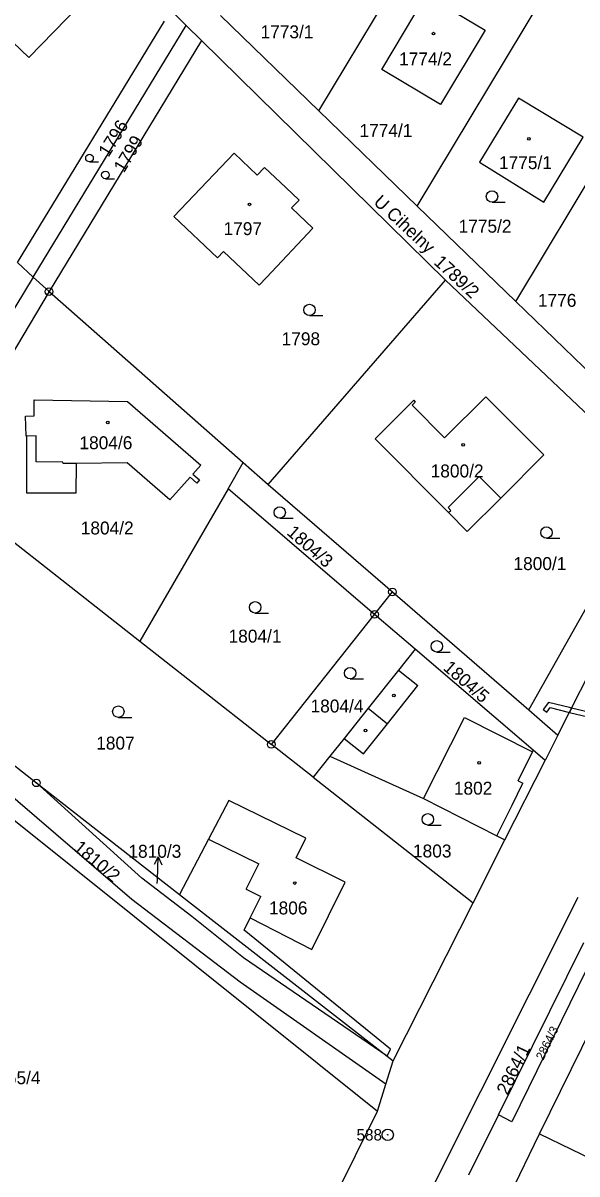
# Model space of a CAD drawing. Extents: x -562167 to -556918, y -1077891 to -1070763.
# Drawn here: x -560383.3 to -560310.5, y -1076020.6 to -1075869.3 of the extents above; entities that cross this region are included whole.
import ezdxf

# ---------------------------------------------------------------- set-up
doc = ezdxf.new("R2010")
doc.units = 0
for name, color, linetype in [('Hranice parcel', 7, 'Continuous'), ('Parcelní čísla', 7, 'Continuous'), ('Pop  PČ popisy', 7, 'Continuous'), ('Vnitřní kresba', 7, 'Continuous'), ('Věcná břemena k části', 7, 'Continuous'), ('Značky bodu BP', 7, 'Continuous'), ('Značky budov', 7, 'Continuous'), ('Značky kultur', 7, 'Continuous')]:
    doc.layers.add(name, color=color, linetype=linetype)

msp = doc.modelspace()

# ---------------------------------------------------------------- linework, layer by layer
at = {"layer": 'Hranice parcel'}
for p, q in [((-560344.44, -1075880.81), (-560327.39, -1075852.49)), ((-560331.52, -1075893.35), (-560314.48, -1075865.02)), ((-560361.86, -1075869.59), (-560363.85, -1075867.62)), ((-560357.35, -1075868.27), (-560344.44, -1075880.81)), ((-560384.03, -1075900.74), (-560364.69, -1075868.99)), ((-560381.96, -1075902.65), (-560361.86, -1075869.59)), ((-560359.86, -1075871.55), (-560361.86, -1075869.59)), ((-560359.86, -1075871.55), (-560379.88, -1075904.56)), ((-560327.78, -1075903.07), (-560359.86, -1075871.55)), ((-560318.55, -1075905.86), (-560301.63, -1075877.64)), ((-560344.44, -1075880.81), (-560331.52, -1075893.35)), ((-560331.52, -1075893.35), (-560318.55, -1075905.86)), ((-560384.03, -1075900.74), (-560381.96, -1075902.65)), ((-560381.96, -1075902.65), (-560397.07, -1075927.67)), ((-560381.96, -1075902.65), (-560379.88, -1075904.56)), ((-560351.07, -1075929.92), (-560327.78, -1075903.07)), ((-560299.96, -1075929.47), (-560327.78, -1075903.07)), ((-560379.88, -1075904.56), (-560394.69, -1075929.54)), ((-560379.88, -1075904.56), (-560354.36, -1075927.03)), ((-560318.55, -1075905.86), (-560305.73, -1075918.26)), ((-560356.35, -1075930.48), (-560354.36, -1075927.03)), ((-560354.36, -1075927.03), (-560351.07, -1075929.92)), ((-560316.85, -1075959.58), (-560299.96, -1075929.47)), ((-560394.69, -1075929.54), (-560367.94, -1075950.54)), ((-560356.35, -1075930.48), (-560367.94, -1075950.54)), ((-560337.1, -1075947.01), (-560356.35, -1075930.48)), ((-560351.07, -1075929.92), (-560334.76, -1075944.06)), ((-560313.03, -1075962.89), (-560298.93, -1075934.98)), ((-560337.1, -1075947.01), (-560334.76, -1075944.06)), ((-560334.76, -1075944.06), (-560316.85, -1075959.58)), ((-560350.67, -1075964.11), (-560337.1, -1075947.01)), ((-560331.78, -1075951.57), (-560337.1, -1075947.01)), ((-560406.88, -1075949.3), (-560381.54, -1075969.16)), ((-560367.94, -1075950.54), (-560350.67, -1075964.11)), ((-560345.16, -1075968.43), (-560350.67, -1075964.11)), ((-560313.03, -1075962.89), (-560314.71, -1075966.22)), ((-560342.97, -1075965.66), (-560345.16, -1075968.43)), ((-560319.99, -1075976.66), (-560314.71, -1075966.22)), ((-560345.16, -1075968.43), (-560324.16, -1075984.92)), ((-560381.54, -1075969.16), (-560362.72, -1075983.85)), ((-560324.16, -1075984.92), (-560319.99, -1075976.66)), ((-560362.72, -1075983.85), (-560335.46, -1076005.11)), ((-560334.67, -1076005.72), (-560324.16, -1075984.92)), ((-560320.84, -1076012.83), (-560309.62, -1075990.16)), ((-560335.46, -1076005.11), (-560334.67, -1076005.72)), ((-560335.62, -1076008.76), (-560334.67, -1076005.72)), ((-560336.72, -1076012.32), (-560335.62, -1076008.76)), ((-560359.95, -1076059.13), (-560336.72, -1076012.32)), ((-560320.84, -1076012.83), (-560324.76, -1076020.74)), ((-560319.06, -1076013.73), (-560320.84, -1076012.83))]:
    msp.add_line(p, q, dxfattribs=at)
for points in [[(-560389.85, -1075866.82), (-560382.51, -1075873.8), (-560375.94, -1075867.05), (-560382.07, -1075861.22)], [(-560328.44, -1075879.95), (-560336.17, -1075875.38), (-560330.35, -1075865.54), (-560322.6, -1075870.17), (-560328.44, -1075879.95)], [(-560314.87, -1075892.81), (-560309.71, -1075884.28), (-560318.18, -1075879.13), (-560323.33, -1075887.57), (-560314.87, -1075892.81)], [(-560347.03, -1075892.53), (-560348.76, -1075890.89), (-560351.56, -1075888.23), (-560352.53, -1075889.24), (-560355.57, -1075886.35), (-560361.73, -1075892.85), (-560363.47, -1075894.69), (-560357.74, -1075900.14), (-560356.95, -1075899.31), (-560352.26, -1075903.74), (-560351.31, -1075902.73), (-560345.2, -1075896.22), (-560348.01, -1075893.55), (-560347.03, -1075892.53)], [(-560360.12, -1075929.33), (-560360.48, -1075929.74), (-560361.35, -1075928.96), (-560363.99, -1075931.95), (-560369.62, -1075927.08), (-560376.3, -1075927.16), (-560376.34, -1075931.05), (-560382.78, -1075931.07), (-560382.8, -1075923.56), (-560382.9, -1075923.56), (-560382.95, -1075920.93), (-560381.85, -1075920.9), (-560381.83, -1075918.78), (-560369.58, -1075919.01), (-560359.94, -1075927.38), (-560360.99, -1075928.56), (-560360.12, -1075929.33)], [(-560327.41, -1075933.63), (-560337.04, -1075923.93), (-560331.97, -1075918.85), (-560331.77, -1075919.09), (-560332.18, -1075919.48), (-560327.9, -1075923.78), (-560322.48, -1075918.39), (-560314.87, -1075926.03), (-560320.54, -1075931.71), (-560324.94, -1075936.11), (-560327.41, -1075933.63)], [(-560335.62, -1076008.76), (-560354.78, -1075995.35), (-560368.98, -1075984.48), (-560391.5, -1075965.15), (-560407.79, -1075951.5)], [(-560331.78, -1075951.57), (-560333.98, -1075954.33), (-560337.96, -1075959.34), (-560341.1, -1075963.31), (-560342.97, -1075965.66)], [(-560314.71, -1075966.22), (-560316.27, -1075964.88), (-560331.78, -1075951.57)], [(-560409.09, -1075954.66), (-560384.71, -1075973.85), (-560336.72, -1076012.32)], [(-560316.85, -1075959.58), (-560314.73, -1075961.42), (-560313.03, -1075962.89)], [(-560342.97, -1075965.66), (-560330.66, -1075971.23), (-560321.04, -1075976.12), (-560319.99, -1075976.66)], [(-560335.46, -1076005.11), (-560354.33, -1075992.19), (-560361.1, -1075986.74), (-560367.69, -1075981.69), (-560381.54, -1075969.16)], [(-560335.46, -1076005.11), (-560335.01, -1076004.2), (-560354.25, -1075988.53), (-560353.46, -1075986.93), (-560345.36, -1075991.08), (-560340.99, -1075982.23), (-560347.42, -1075979), (-560346.14, -1075976.42), (-560356.26, -1075971.48), (-560358.91, -1075976.55), (-560362.72, -1075983.85)], [(-560329.29, -1076028.06), (-560329.52, -1076027.63), (-560329.7, -1076027.17), (-560329.99, -1076025.7), (-560330.08, -1076025.18), (-560330.12, -1076024.66), (-560329.9, -1076023.7), (-560329.53, -1076022.45), (-560310.34, -1075984.19)], [(-560307.96, -1075990.95), (-560308.05, -1075991.55), (-560308.19, -1075991.48), (-560319.06, -1076013.73)]]:
    msp.add_lwpolyline(points, dxfattribs=at)
at = {"layer": 'Pop  PČ popisy'}
for p, q in [((-560365.53, -1075978.9), (-560366.06, -1075979.88)), ((-560365.63, -1075981.9), (-560365.53, -1075978.9)), ((-560365.53, -1075978.9), (-560365.06, -1075979.92)), ((-560365.65, -1075982.41), (-560365.63, -1075981.9))]:
    msp.add_line(p, q, dxfattribs=at)
at = {"layer": 'Vnitřní kresba'}
for p, q in [((-560381.57, -1075923.54), (-560382.8, -1075923.56)), ((-560381.55, -1075926.94), (-560381.57, -1075923.54)), ((-560378.05, -1075926.99), (-560381.55, -1075926.94)), ((-560378.04, -1075927.19), (-560378.05, -1075926.99)), ((-560376.3, -1075927.16), (-560378.04, -1075927.19)), ((-560327.46, -1075932.97), (-560323.37, -1075928.88)), ((-560323.37, -1075928.88), (-560320.54, -1075931.71)), ((-560327.46, -1075932.97), (-560327.1, -1075933.33)), ((-560327.41, -1075933.63), (-560327.1, -1075933.33)), ((-560333.98, -1075954.33), (-560331.41, -1075956.37)), ((-560335.4, -1075961.38), (-560331.41, -1075956.37)), ((-560337.96, -1075959.34), (-560335.4, -1075961.38)), ((-560330.66, -1075971.23), (-560325.3, -1075960.59)), ((-560325.3, -1075960.59), (-560316.37, -1075965.1)), ((-560338.56, -1075965.36), (-560335.4, -1075961.38)), ((-560341.1, -1075963.31), (-560338.56, -1075965.36)), ((-560318.26, -1075968.91), (-560316.37, -1075965.1)), ((-560316.37, -1075965.1), (-560316.27, -1075964.88)), ((-560319.04, -1075972.09), (-560317.62, -1075969.22)), ((-560318.26, -1075968.91), (-560317.62, -1075969.22)), ((-560321.04, -1075976.12), (-560319.04, -1075972.09)), ((-560358.91, -1075976.55), (-560352.3, -1075979.79)), ((-560353.97, -1075983.13), (-560352.3, -1075979.79)), ((-560353.97, -1075983.13), (-560352.06, -1075984.11)), ((-560353.46, -1075986.93), (-560352.06, -1075984.11)), ((-560315.44, -1076015.32), (-560304.54, -1075993.08)), ((-560319.34, -1076023.39), (-560315.44, -1076015.32)), ((-560315.44, -1076015.32), (-560304.89, -1076020.44))]:
    msp.add_line(p, q, dxfattribs=at)
at = {"layer": 'Věcná břemena k části'}
for points in [[(-560314.46, -1075959.88), (-560314.03, -1075959.27), (-560311.66, -1075959.85), (-560311.51, -1075959.89), (-560311.23, -1075959.34), (-560311.52, -1075959.27), (-560314.27, -1075958.59), (-560314.95, -1075959.53)], [(-560311.23, -1075959.34), (-560311.51, -1075959.89), (-560299.82, -1075962.66), (-560299.55, -1075962.11)]]:
    msp.add_lwpolyline(points, close=True, dxfattribs=at)
at = {"layer": 'Značky bodu BP'}
for centre, radius in [((-560379.88, -1075904.56), 0.5), ((-560379.88, -1075904.56), 0.0303), ((-560334.76, -1075944.06), 0.5), ((-560334.76, -1075944.06), 0.0303), ((-560337.1, -1075947.01), 0.5), ((-560337.1, -1075947.01), 0.0303), ((-560350.67, -1075964.11), 0.5), ((-560350.67, -1075964.11), 0.0303), ((-560381.54, -1075969.16), 0.5), ((-560381.54, -1075969.16), 0.0303), ((-560335.38, -1076015.44), 0.75), ((-560335.38, -1076015.44), 0.03)]:
    msp.add_circle(centre, radius, dxfattribs=at)
at = {"layer": 'Značky budov'}
for centre in [(-560329.36, -1075870.65), (-560316.82, -1075884.49), (-560353.55, -1075893.1), (-560372.17, -1075921.78), (-560325.48, -1075924.71), (-560334.56, -1075957.67), (-560338.29, -1075962.29), (-560323.38, -1075966.54), (-560347.6, -1075982.33)]:
    msp.add_circle(centre, 0.175, dxfattribs=at)
at = {"layer": 'Značky kultur'}
for p, q in [((-560374.56, -1075887.51), (-560373.38, -1075887.51)), ((-560372.46, -1075889.72), (-560371.29, -1075889.72)), ((-560321.68, -1075892.81), (-560319.93, -1075892.81)), ((-560345.66, -1075907.73), (-560343.91, -1075907.73)), ((-560349.57, -1075934.37), (-560347.82, -1075934.37)), ((-560314.53, -1075937), (-560312.78, -1075937)), ((-560352.8, -1075946.83), (-560351.05, -1075946.83)), ((-560328.94, -1075951.96), (-560327.19, -1075951.96)), ((-560340.31, -1075955.49), (-560338.56, -1075955.49)), ((-560370.77, -1075960.55), (-560369.02, -1075960.55)), ((-560330.11, -1075974.71), (-560328.36, -1075974.71))]:
    msp.add_line(p, q, dxfattribs=at)
for centre, radius in [((-560374.56, -1075887.01), 0.502), ((-560372.47, -1075889.22), 0.502), ((-560321.68, -1075892.06), 0.75), ((-560345.66, -1075906.98), 0.75), ((-560349.57, -1075933.62), 0.75), ((-560314.53, -1075936.25), 0.75), ((-560352.8, -1075946.08), 0.75), ((-560328.94, -1075951.21), 0.75), ((-560340.31, -1075954.74), 0.75), ((-560370.77, -1075959.8), 0.75), ((-560330.11, -1075973.96), 0.75)]:
    msp.add_circle(centre, radius, dxfattribs=at)

# ---------------------------------------------------------------- texts
at = {"layer": 'Parcelní čísla'}
for s, p in [('1773/1', (-560352.09, -1075871.26)), ('1774/2', (-560333.89, -1075874.82)), ('1774/1', (-560339.09, -1075884.24)), ('1775/1', (-560320.76, -1075888.46)), ('1797', (-560356.95, -1075897.14)), ('1775/2', (-560326.07, -1075896.82)), ('1776', (-560315.65, -1075906.57)), ('1798', (-560349.32, -1075911.62)), ('1804/6', (-560375.88, -1075925.29)), ('1800/2', (-560329.74, -1075929)), ('1804/2', (-560375.71, -1075936.5)), ('1800/1', (-560318.86, -1075941.18)), ('1804/1', (-560356.29, -1075950.72)), ('1804/4', (-560345.52, -1075959.91)), ('1807', (-560373.68, -1075964.78)), ('1802', (-560326.69, -1075970.71)), ('1810/3', (-560369.45, -1075979.01)), ('1803', (-560332.06, -1075978.97)), ('1806', (-560350.98, -1075986.46)), ('2655/4', (-560387.94, -1076008.78))]:
    msp.add_text(s, height=1.7, dxfattribs=at).set_placement(p)
for s, height, rotation, p in [('1796', 1.7, 58, (-560372.07, -1075886.98)), ('1799', 1.7, 59, (-560370.04, -1075889.05)), ('1789/2', 1.7, 317, (-560329.43, -1075900.85)), ('1804/3', 1.7, 319, (-560348.75, -1075936.42)), ('1804/5', 1.7, 319, (-560328.21, -1075954.2)), ('1810/2', 1.7, 320, (-560376.77, -1075977.88)), ('2864/3', 1.139, 64, (-560314.95, -1076005.71)), ('2864/1', 1.7, 64, (-560319.64, -1076010.32))]:
    msp.add_text(s, height=height, rotation=rotation, dxfattribs=at).set_placement(p)
at = {"layer": 'Pop  PČ popisy'}
msp.add_text('U Cihelny', height=1.7, rotation=317, dxfattribs=at).set_placement((-560337.35, -1075892.95))
at = {"layer": 'Značky bodu BP'}
msp.add_text('588', height=1.5, dxfattribs=at).set_placement((-560339.48, -1076016.19))

doc.saveas('drawing.dxf')
